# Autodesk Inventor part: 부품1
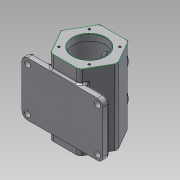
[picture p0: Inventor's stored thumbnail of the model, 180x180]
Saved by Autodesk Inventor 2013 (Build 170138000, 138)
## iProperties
Created: 2021-06
Part Number: 부품1
Material: 알루미늄 6061
Document SubType Name: Modeling
Designer: hana-max10
Mass: 1501.14 g
Surface Area: 1103.23 cm^2
Volume: 553.925 cm^3
Density: 2.71 g/cm^3
Author: hana-max10
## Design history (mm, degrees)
sketch "스케치1"
  geometry: L1 (26.25, 45.466)-(52.5, 0); L2 (52.5, 0)-(26.25, -45.466); L3 (26.25, -45.466)-(-26.25, -45.466); L4 (-26.25, -45.466)-(-52.5, 0); L5 (-52.5, 0)-(-26.25, 45.466); L6 (-26.25, 45.466)-(26.25, 45.466); L7 (-73.5, 0)-(73.5, 0) reference; L8 (0, -63.653)-(0, 63.653) reference; 2 further points
  constraints: 12 end point, 1 coincident, 1 perpendicular, 13 other
  dimensions: "d0" = 105 distance of L1.end L4.end
extrude "돌출1" new body sketch "스케치1" distance "d1" = 140; taper "d2" = 0 deg
node "작업 평면1"
sketch "스케치2"
  geometry: L1 (-75, -38)-(75, -38); L2 (75, -38)-(75, -50); L3 (75, -50)-(-75, -50); L4 (-75, -50)-(-75, -38); L5 (-73.5, 0)-(73.5, 0) reference; L6 (0, -68.459)-(0, 64.454) reference; 1 further point
  constraints: 8 end point, 2 parallel, 1 horizontal, 1 perpendicular, 1 other
  dimensions: "d4" = 12 distance of L1.end L2.end; "d6" = 50 distance between parallel lines of L3 L5; "d7" = 150 distance of L2.end L3.end
extrude "돌출2" join sketch "스케치2" distance "d8" = 45; taper "d9" = 0 deg; dims "d21" = 55, "d22" = 0
sketch "스케치3"
  geometry: L1 (0, 140)-(-45.466, 140) reference; L2 (0, 140)-(30, 140); L3 (37.5, 128)-(37.5, 12); L4 (30, 128)-(37.5, 128); L5 (30, 140)-(30, 128); L6 (30, 12)-(30, 0); L7 (37.5, 12)-(30, 12); L8 (0, 140)-(0, 0); L9 (0, 0)-(30, 0); L10 (0, 146.302)-(0, -28.105)
  constraints: 18 end point, 3 horizontal, 3 perpendicular, 2 point on line, 1 parallel, 1 vertical
  dimensions: "d13" = 30 distance of L2.start L2.end; "d15" = 12 distance of L2.end L4.start; "d16" = 12 distance of L6.start L6.end; "d17" = 116 distance of L3.start L3.end; "d18" = 37.5 distance between parallel lines of L8 L3; "d19" = 30 distance between parallel lines of L8 L6
revolve "회전1" sketch "스케치3" stored, may be unused: angle "d20" = 90 deg
sketch "스케치4"
  geometry: L1 (52.5, -140)-(0, -140) reference; L2 (52.5, 0)-(52.5, -140) reference; C1 r 20 at (26.25, -40); C2 r 20 at (26.25, -100); 1 further point
  constraints: 2 centre point
  dimensions: "d23" = 60 distance of C2.centre C1.centre; "d25" = 40 diameter of C1; "d26" = 40 diameter of C2; "d27" = 26.25 distance from line of L2 C2.centre; "d28" = 26.25 distance from line of L2 C1.centre; "d29" = 40 distance from line of L1 C2.centre
extrude "돌출3" join sketch "스케치4" distance "d30" = 7.034; taper "d31" = 0 deg
sketch "스케치5"
  geometry: L1 (26.25, 40)-(26.25, -100) reference; C1 r 20 at (0, 0) reference; 3 further points
  constraints: 1 coincident
  dimensions: "d32" = 60 distance of point (0, 0) point (0, -60); "d34" = 26.25 distance from line of L1 point (0, -60)
hole "구멍1" sketch "스케치5" at (0, 0), (0, -60) diameter "d35" = 25; stored, may be unused: countersink angle "d39" = 90 deg, drill point angle "d41" = 0 deg; dims "d36" = 6, "d37" = 30, "d38" = 8, "d40" = 20
sketch "스케치6"
  geometry: L1 (52.5, 0)-(26.25, 45.466) reference; L2 (26.25, 45.466)-(-26.25, 45.466) reference; L3 (-26.25, 45.466)-(-52.5, 0) reference; L4 (-52.5, 0)-(-26.25, -45.466) reference; L5 (-26.25, -45.466)-(26.25, -45.466) reference; L6 (26.25, -45.466)-(52.5, 0) reference; C1 r 30 at (0, 0) reference
sketch "스케치7"
  geometry: C1 r 30 at (0, 0) reference; A1 r 40 centre (0, 0) between (0, 40) and (40, 0); 2 further points
  constraints: 4 point on circle, 1 centre point, 1 coincident
  dimensions: "d42" = 80 diameter of A1
hole "구멍2" sketch "스케치7" at (0, 40), (40, 0), (0, -40), (-40, 0) diameter "d44" = 4.134; stored, may be unused: countersink angle "d48" = 90 deg, drill point angle "d50" = 118 deg; dims "d45" = 8, "d46" = 30, "d47" = 8, "d49" = 10
sketch "스케치8"
  geometry: L1 (0, 0)-(-47.315, 47.315); L2 (-105, 0)-(105, 0) reference; L3 (0, -70.5)-(0, 73) reference; L4 (0, 0)-(52.5, 52.5); L5 (0, 0)-(38.7, -38.7); L6 (0, 0)-(-44.373, -44.373); C1 r 30 at (0, 0) reference; A1 r 40 centre (0, 0) between (-28.284, 28.284) and (-28.284, -28.284); 2 further points
  constraints: 8 end point, 4 point on circle, 4 point on line, 1 centre point, 1 coincident, 1 perpendicular
  dimensions: "d51" = 80 diameter of A1; "d52" = 45 deg angle of L3 L1; "d55" = 45 deg angle of L2 L5; "d57" = 45 deg angle of L3 L6
hole "구멍3" sketch "스케치8" at (-28.284, -28.284), (-28.284, 28.284), (28.284, 28.284), (28.284, -28.284) diameter "d59" = 4.134; stored, may be unused: countersink angle "d63" = 90 deg, drill point angle "d65" = 118 deg; dims "d60" = 8, "d61" = 30, "d62" = 8, "d64" = 10
fillet "모깎기1" dims "d66" = 10
sketch "스케치9" dims "d41" = 0
  geometry: C1 r 5.5 at (-95.561, 90); C2 r 5.5 at (34.439, 10); C3 r 5.5 at (-95.561, 10); C4 r 5.5 at (34.439, 90); A1 r 10 centre (34.439, 90) between (44.439, 90) and (34.439, 100) reference; A2 r 10 centre (34.439, 10) between (34.439, 0) and (44.439, 10) reference; A3 r 10 centre (-95.561, 90) between (-95.561, 100) and (-105.561, 90) reference; A4 r 10 centre (-95.561, 10) between (-105.561, 10) and (-95.561, 0) reference; 1 further point
  constraints: 4 centre point, 4 concentric
  dimensions: "d67" = 11 diameter of C1; "d69" = 11 diameter of C4; "d70" = 11 diameter of C2; "d71" = 11 diameter of C3
extrude "돌출4" cut sketch "스케치9" distance "d72" = 12; taper "d73" = 0 deg
sketch "스케치10"
  geometry: L1 (0, 0)-(-34.439, 0) reference; L2 (-44.439, 90)-(-44.439, 10) reference; 2 further points
  constraints: 1 other
  dimensions: "d74" = 14 distance from line of L2 point (-30.439, 50); "d75" = 50 distance from line of L1 point (-30.439, 50)
feature "엠보싱1" sketch "스케치10" dims "d0" = 105, "d13" = 30, "d15" = 12, "d16" = 12, "d17" = 116, "d18" = 37.5, "d19" = 30, "d76" = 0.5, "d77" = 0
fillet "모깎기2" dims "d78" = 8
fillet "모깎기3" dims "d79" = 5
chamfer "모따기1" distance "d80" = 1; stored, may be unused: second distance "d81" = 2, angle "d82" = 45 deg
fillet "모깎기4" dims "d83" = 3
fillet "모깎기5" dims "d84" = 3
fillet "모깎기6" dims "d85" = 3
chamfer "모따기2" distance "d86" = 1; stored, may be unused: second distance "d87" = 2, angle "d88" = 45 deg
node "솔리드1"
